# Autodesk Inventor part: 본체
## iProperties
Created: 2014-11
Part Number: 본체
Document SubType Name: Modeling
Designer: elite
Density: 2.71 g/cm^3
Material: 알루미늄-6061
Mass: 2881.81 g
Surface Area: 2080.34 cm^2
Volume: 1063.4 cm^3
Author: elite
